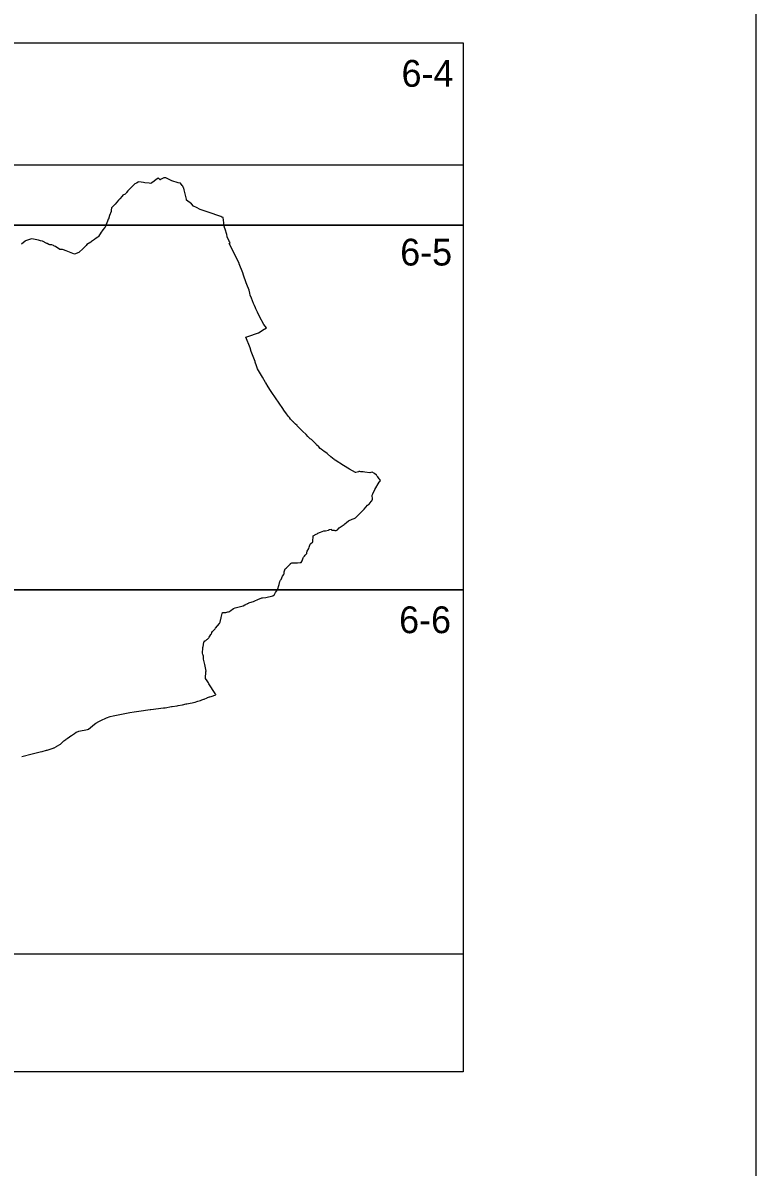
# Model space of a CAD drawing. Extents: x -449577 to -436680, y -1132317 to -1125726.
# Drawn here: x -443806.9 to -443555.6, y -1128354.9 to -1127962.6 of the extents above; entities that cross this region are included whole.
import ezdxf

# ---------------------------------------------------------------- set-up
doc = ezdxf.new("R2010")
doc.units = 0
for name, color, linetype in [('Vrstva 1', 7, 'Continuous'), ('Vrstva 10', 7, 'Continuous'), ('Vrstva 4', 7, 'Continuous')]:
    doc.layers.add(name, color=color, linetype=linetype)

msp = doc.modelspace()

# ---------------------------------------------------------------- linework, layer by layer
at = {"layer": 'Vrstva 1'}
msp.add_lwpolyline([(-445040.56, -1127667.99), (-445040.56, -1128717.99), (-443555.56, -1128717.99), (-443555.56, -1127667.99)], close=True, dxfattribs=at)
msp.add_lwpolyline([(-443807.27, -1128214.11), (-443803.73, -1128213.24), (-443800.96, -1128212.57), (-443800.29, -1128212.36), (-443798.8, -1128212), (-443798.59, -1128211.94), (-443797.16, -1128211.55), (-443796.56, -1128211.29), (-443796.34, -1128211.19), (-443796.18, -1128211.13), (-443795.36, -1128210.68), (-443795.3, -1128210.64), (-443793.99, -1128209.86), (-443792.84, -1128208.81), (-443792.19, -1128208.31), (-443792.06, -1128208.2), (-443792.04, -1128208.19), (-443791.88, -1128208.06), (-443791.73, -1128207.96), (-443790.93, -1128207.4), (-443790.87, -1128207.36), (-443790.8, -1128207.31), (-443790.29, -1128206.96), (-443789.92, -1128206.7), (-443789.26, -1128206.24), (-443788.67, -1128205.83), (-443788.51, -1128205.86), (-443788.5, -1128205.86), (-443788.48, -1128205.84), (-443787.75, -1128205.45), (-443784.79, -1128204.87), (-443784.37, -1128204.72), (-443782.34, -1128203.09), (-443781.87, -1128202.75), (-443781.84, -1128202.73), (-443781.48, -1128202.47), (-443781.3, -1128202.35), (-443779.91, -1128201.65), (-443778.5, -1128201.01), (-443778.2, -1128200.86), (-443776.94, -1128200.4), (-443775.94, -1128200.15), (-443770.23, -1128199.09), (-443768.81, -1128198.83), (-443767.1, -1128198.58), (-443763.23, -1128198.01), (-443762.99, -1128197.98), (-443758.69, -1128197.46), (-443758.16, -1128197.4), (-443756.01, -1128197.04), (-443755.69, -1128196.99), (-443754.03, -1128196.72), (-443753.63, -1128196.65), (-443752.22, -1128196.36), (-443750.93, -1128196.09), (-443750.72, -1128196.05), (-443749.55, -1128195.82), (-443748.88, -1128195.69), (-443748.86, -1128195.69), (-443747.95, -1128195.48), (-443747.88, -1128195.46), (-443747.23, -1128195.3), (-443746.88, -1128195.19), (-443745.99, -1128194.9), (-443745.55, -1128194.75), (-443744.9, -1128194.51), (-443744.78, -1128194.47), (-443743.69, -1128193.98), (-443743.69, -1128193.98), (-443743.57, -1128193.94), (-443742.92, -1128193.71), (-443742.83, -1128193.68), (-443742.4, -1128193.52), (-443740.74, -1128192.94), (-443740.76, -1128192.89), (-443740.87, -1128192.72), (-443741.03, -1128192.49), (-443741.25, -1128192.17), (-443742.95, -1128189.53), (-443743.16, -1128189.18), (-443743.33, -1128188.91), (-443743.77, -1128188.2), (-443744.3, -1128187.35), (-443744.14, -1128184.99), (-443744.13, -1128184.9), (-443744.52, -1128182.6), (-443744.52, -1128182.58), (-443744.53, -1128182.56), (-443744.53, -1128182.56), (-443744.53, -1128182.53), (-443744.94, -1128180.7), (-443744.95, -1128180.51), (-443745.01, -1128179.71), (-443745.11, -1128179.43), (-443745.12, -1128179.41), (-443745.23, -1128179.19), (-443745.27, -1128179.11), (-443745.28, -1128178.73), (-443745.31, -1128178.03), (-443745.26, -1128177.54), (-443745.26, -1128177.52), (-443745.17, -1128176.66), (-443745.15, -1128176.55), (-443744.86, -1128174.91), (-443744.78, -1128174.83), (-443744.48, -1128174.49), (-443744.42, -1128174.42), (-443744.16, -1128174.3), (-443744.1, -1128174.24), (-443743.84, -1128174.04), (-443743.61, -1128173.86), (-443743.4, -1128173.7), (-443743.34, -1128173.66), (-443743.26, -1128173.53), (-443743.18, -1128173.41), (-443743.07, -1128173.24), (-443742.85, -1128172.91), (-443742.43, -1128172.26), (-443742.3, -1128172.01), (-443742.29, -1128172), (-443742.15, -1128171.71), (-443742.1, -1128171.62), (-443741.92, -1128171.29), (-443741.78, -1128171.14), (-443741.48, -1128170.83), (-443741.31, -1128170.65), (-443741.03, -1128170.3), (-443740.9, -1128170.13), (-443740.21, -1128169.28), (-443739.55, -1128168.47), (-443739.26, -1128168.11), (-443739.02, -1128166.94), (-443738.96, -1128166.71), (-443738.89, -1128166.43), (-443738.57, -1128165.12), (-443738.49, -1128164.84), (-443738.49, -1128164.81), (-443738.47, -1128164.76), (-443738.31, -1128164.75), (-443738.29, -1128164.75), (-443738.05, -1128164.75), (-443737.36, -1128164.73), (-443737.35, -1128164.73), (-443737.32, -1128164.73), (-443736.64, -1128164.55), (-443736.44, -1128164.49), (-443736.02, -1128164.38), (-443736, -1128164.37), (-443735.94, -1128164.31), (-443735.64, -1128164.03), (-443735.52, -1128163.95), (-443735.18, -1128163.69), (-443734.76, -1128163.37), (-443734.69, -1128163.35), (-443734.13, -1128163.19), (-443731.43, -1128162.43), (-443730.84, -1128162.16), (-443730.51, -1128162), (-443730.46, -1128161.98), (-443730.36, -1128161.93), (-443730, -1128161.75), (-443729.95, -1128161.73), (-443729.92, -1128161.71), (-443729.91, -1128161.71), (-443729.88, -1128161.69), (-443729.57, -1128161.54), (-443729.51, -1128161.5), (-443729.4, -1128161.45), (-443728.32, -1128161.12), (-443727.89, -1128160.94), (-443727.37, -1128160.72), (-443726.36, -1128160.31), (-443724.94, -1128159.68), (-443724.8, -1128159.67), (-443723.67, -1128159.62), (-443721.27, -1128159.06), (-443720.74, -1128158.66), (-443720.67, -1128158.54), (-443720.58, -1128158.36), (-443720.32, -1128157.85), (-443719.97, -1128157.42), (-443719.95, -1128157.39), (-443719.74, -1128157.1), (-443719.63, -1128156.94), (-443719.62, -1128156.93), (-443719.08, -1128155.15), (-443719.07, -1128155.12), (-443718.87, -1128154.17), (-443718.61, -1128153.71), (-443718.42, -1128153.38), (-443717.87, -1128152.26), (-443717.49, -1128151.75), (-443717.46, -1128151.62), (-443717.39, -1128151.32), (-443717.36, -1128151.18), (-443717.3, -1128150.93), (-443717.28, -1128150.83), (-443716.96, -1128149.82), (-443716.95, -1128149.81), (-443716.66, -1128149.53), (-443716, -1128148.9), (-443715.95, -1128148.85), (-443715.48, -1128148.37), (-443715.22, -1128148.11), (-443715.12, -1128148), (-443714.75, -1128147.68), (-443714.71, -1128147.68), (-443714.7, -1128147.68), (-443714.29, -1128147.67), (-443714.12, -1128147.68), (-443713.49, -1128147.7), (-443712.78, -1128147.7), (-443711.81, -1128147.61), (-443711.78, -1128147.61), (-443711.53, -1128147.58), (-443711.31, -1128147.22), (-443711.26, -1128147.09), (-443711.24, -1128147.04), (-443711.22, -1128146.98), (-443710.86, -1128145.96), (-443710.72, -1128145.79), (-443710.62, -1128145.68), (-443710.58, -1128145.64), (-443710.52, -1128145.56), (-443710.4, -1128145.43), (-443710.13, -1128145.11), (-443710.04, -1128145.01), (-443709.94, -1128144.89), (-443709.6, -1128144.5), (-443709.53, -1128144.11), (-443709.47, -1128143.8), (-443709.4, -1128143.67), (-443708.85, -1128142.75), (-443708.74, -1128142.36), (-443708.55, -1128141.66), (-443708.43, -1128141.37), (-443708.14, -1128141.1), (-443707.59, -1128140.59), (-443707.52, -1128140.53), (-443707.42, -1128138.42), (-443706.4, -1128137.93), (-443706, -1128137.72), (-443705.75, -1128137.59), (-443705.46, -1128137.43), (-443705.24, -1128137.35), (-443704.9, -1128137.22), (-443704.85, -1128137.21), (-443703.76, -1128136.8), (-443703.75, -1128136.8), (-443703.26, -1128136.74), (-443703.18, -1128136.72), (-443702.15, -1128136.46), (-443702, -1128136.42), (-443701.91, -1128136.39), (-443701.74, -1128136.34), (-443701.21, -1128136.17), (-443701.21, -1128136.17), (-443701.2, -1128136.18), (-443701.2, -1128136.18), (-443701.17, -1128136.24), (-443701.04, -1128136.46), (-443700.16, -1128136.56), (-443699.96, -1128136.58), (-443699.6, -1128136.62), (-443699.51, -1128136.58), (-443699.08, -1128136.4), (-443698.43, -1128135.69), (-443696.79, -1128134.53), (-443696.7, -1128134.46), (-443696.53, -1128134.35), (-443696.02, -1128133.93), (-443695.27, -1128133.33), (-443694, -1128132.76), (-443693.38, -1128132.49), (-443692.84, -1128132.25), (-443692.78, -1128132.22), (-443691.13, -1128130.55), (-443690.29, -1128129.66), (-443689.93, -1128129.28), (-443688.74, -1128127.92), (-443688.14, -1128127.46), (-443688.09, -1128127.42), (-443687.25, -1128126.41), (-443687.05, -1128125.84), (-443687.14, -1128124.51), (-443686.92, -1128124.02), (-443686.28, -1128122.57), (-443684.82, -1128120.09), (-443684.79, -1128120.04), (-443684.79, -1128120.04), (-443684.77, -1128120.01), (-443684.74, -1128119.97), (-443684.59, -1128119.78), (-443684.33, -1128119.44), (-443684.59, -1128119.14), (-443684.73, -1128118.92), (-443685.2, -1128118.18), (-443685.4, -1128117.99), (-443685.55, -1128117.83), (-443685.74, -1128117.63), (-443686.32, -1128117.06), (-443687.17, -1128116.59), (-443687.62, -1128116.77), (-443687.95, -1128116.89), (-443689.7, -1128116.62), (-443690.31, -1128116.53), (-443690.45, -1128116.52), (-443691.04, -1128116.5), (-443691.42, -1128116.45), (-443691.58, -1128116.42), (-443691.62, -1128116.42), (-443691.65, -1128116.41), (-443691.65, -1128116.41), (-443691.68, -1128116.42), (-443691.78, -1128116.45), (-443691.91, -1128116.48), (-443692.81, -1128116.72), (-443692.88, -1128116.69), (-443694.95, -1128115.65), (-443696.97, -1128114.37), (-443699.88, -1128112.55), (-443700.04, -1128112.41), (-443700.08, -1128112.38), (-443700.17, -1128112.3), (-443701.31, -1128111.37), (-443702.46, -1128110.32), (-443702.57, -1128110.22), (-443703.78, -1128109.46), (-443704.06, -1128109.23), (-443704.69, -1128108.73), (-443705, -1128108.49), (-443705.5, -1128107.96), (-443706.22, -1128107.2), (-443706.37, -1128107.04), (-443706.83, -1128106.55), (-443707.8, -1128105.52), (-443708, -1128105.41), (-443708, -1128105.41), (-443708.18, -1128105.32), (-443708.38, -1128105.22), (-443709.21, -1128104.39), (-443709.84, -1128103.76), (-443711.02, -1128102.59), (-443711.95, -1128101.65), (-443712.11, -1128101.5), (-443712.55, -1128101.05), (-443712.79, -1128100.81), (-443712.88, -1128100.72), (-443712.92, -1128100.68), (-443713.44, -1128100.16), (-443714.08, -1128099.51), (-443714.16, -1128099.43), (-443714.18, -1128099.41), (-443714.33, -1128099.26), (-443715.16, -1128098.42), (-443715.54, -1128097.92), (-443715.82, -1128097.55), (-443716.14, -1128097.12), (-443716.5, -1128096.64), (-443717.45, -1128095.38), (-443717.82, -1128094.84), (-443720.36, -1128091.1), (-443720.53, -1128090.84), (-443721.3, -1128089.65), (-443721.97, -1128088.64), (-443722.81, -1128087.31), (-443723.61, -1128086.04), (-443723.69, -1128085.91), (-443724.78, -1128084.06), (-443726.46, -1128081.21), (-443726.46, -1128081.2), (-443726.46, -1128081.2), (-443726.47, -1128081.2), (-443726.8, -1128080.22), (-443727.25, -1128078.92), (-443727.31, -1128078.72), (-443728.69, -1128075.21), (-443728.98, -1128073.96), (-443730.46, -1128070.28), (-443729.83, -1128070.08), (-443726.11, -1128068.84), (-443724.14, -1128067.62), (-443723.96, -1128067.51), (-443723.9, -1128067.47), (-443723.7, -1128067.35), (-443723.43, -1128067.18), (-443724.35, -1128065.99), (-443725.76, -1128063.21), (-443726.51, -1128061.74), (-443727.04, -1128060.58), (-443727.06, -1128060.54), (-443727.12, -1128060.41), (-443727.13, -1128060.38), (-443727.15, -1128060.35), (-443727.19, -1128060.26), (-443727.52, -1128059.53), (-443727.84, -1128058.74), (-443728.55, -1128056.97), (-443728.96, -1128055.93), (-443729.11, -1128055.3), (-443729.37, -1128054.17), (-443730.11, -1128052.28), (-443730.31, -1128051.68), (-443731.25, -1128049.05), (-443731.52, -1128048.33), (-443732.71, -1128045.24), (-443732.78, -1128045.06), (-443732.81, -1128044.98), (-443736.16, -1128038.17), (-443735.85, -1128038.03), (-443735.83, -1128038.02), (-443735.93, -1128037.85), (-443736.01, -1128037.75), (-443736.18, -1128037.52), (-443736.24, -1128037.44), (-443736.85, -1128035.96), (-443736.9, -1128035.67), (-443737, -1128035.21), (-443737.01, -1128035.15), (-443737.52, -1128033.31), (-443737.82, -1128032.68), (-443737.83, -1128032.6), (-443737.87, -1128032.24), (-443738.01, -1128031.15), (-443738.29, -1128029.31), (-443738.35, -1128029.29), (-443738.65, -1128029.19), (-443739.03, -1128028.93), (-443739.04, -1128028.93), (-443743.34, -1128027.52), (-443746.13, -1128026.54), (-443747.44, -1128025.92), (-443748.41, -1128025.36), (-443749.13, -1128024.58), (-443750.81, -1128023.31), (-443750.87, -1128023.01), (-443751.45, -1128020.31), (-443751.6, -1128019.77), (-443751.78, -1128019.26), (-443751.83, -1128019.1), (-443752.08, -1128018.58), (-443752.33, -1128018.27), (-443752.91, -1128017.58), (-443753.66, -1128017.37), (-443755.84, -1128016.71), (-443757.93, -1128015.75), (-443758.55, -1128015.75), (-443759.5, -1128016.12), (-443759.63, -1128016.21), (-443759.7, -1128016.26), (-443759.84, -1128016.36), (-443759.88, -1128016.39), (-443759.9, -1128016.37), (-443760.11, -1128016.12), (-443760.36, -1128015.84), (-443760.44, -1128015.74), (-443760.53, -1128015.78), (-443761.04, -1128016.17), (-443761.23, -1128016.32), (-443761.9, -1128016.84), (-443762.65, -1128017.4), (-443762.99, -1128017.62), (-443763.58, -1128017.58), (-443765.06, -1128017.43), (-443765.52, -1128017.34), (-443767.11, -1128017.02), (-443767.41, -1128017.13), (-443767.97, -1128017.48), (-443768.52, -1128017.8), (-443769.01, -1128018.26), (-443769.54, -1128018.75), (-443769.94, -1128019.14), (-443769.95, -1128019.15), (-443770.28, -1128019.49), (-443770.41, -1128019.63), (-443770.92, -1128020.18), (-443771.37, -1128020.73), (-443771.53, -1128020.92), (-443771.89, -1128021.35), (-443772.63, -1128021.68), (-443772.65, -1128021.68), (-443772.85, -1128021.93), (-443773.71, -1128022.95), (-443774.09, -1128023.4), (-443775.22, -1128024.76), (-443775.23, -1128024.77), (-443776.47, -1128025.94), (-443776.59, -1128026.78), (-443776.64, -1128027.15), (-443776.68, -1128027.25), (-443777.16, -1128028.6), (-443777.6, -1128029.84), (-443777.63, -1128029.92), (-443777.93, -1128030.61), (-443778.86, -1128032.79), (-443778.88, -1128032.8), (-443779.45, -1128033.48), (-443779.75, -1128033.83), (-443779.75, -1128033.84), (-443780.09, -1128034.38), (-443780.96, -1128035.77), (-443781.05, -1128035.91), (-443781.22, -1128036.04), (-443781.75, -1128036.43), (-443782.36, -1128036.88), (-443782.36, -1128036.88), (-443783.33, -1128037.51), (-443783.46, -1128037.6), (-443783.64, -1128037.72), (-443784.94, -1128038.58), (-443784.95, -1128038.59), (-443785.21, -1128038.85), (-443785.33, -1128038.97), (-443785.55, -1128039.2), (-443785.83, -1128039.48), (-443786.4, -1128040.05), (-443787.56, -1128041.21), (-443787.76, -1128041.29), (-443789.26, -1128041.86), (-443792.07, -1128040.74), (-443792.07, -1128040.75), (-443792.08, -1128040.77), (-443792.99, -1128040.39), (-443793.3, -1128040.26), (-443793.32, -1128040.26), (-443793.71, -1128040.26), (-443794.19, -1128040.26), (-443795.75, -1128039.27), (-443796.01, -1128039.14), (-443796.3, -1128038.98), (-443796.36, -1128038.95), (-443796.4, -1128038.93), (-443796.94, -1128038.7), (-443796.99, -1128038.7), (-443797, -1128038.7), (-443797.15, -1128038.69), (-443797.27, -1128038.68), (-443797.58, -1128038.66), (-443797.6, -1128038.66), (-443797.6, -1128038.66), (-443797.71, -1128038.62), (-443797.95, -1128038.52), (-443798.55, -1128038.27), (-443798.71, -1128038.2), (-443800.23, -1128037.47), (-443800.85, -1128037.29), (-443801.52, -1128037.09), (-443803.84, -1128036.66), (-443803.85, -1128036.66), (-443804.25, -1128036.77), (-443805.99, -1128037.35), (-443806.12, -1128037.46), (-443807.33, -1128038.42)], dxfattribs=at)
at = {"layer": 'Vrstva 10'}
msp.add_lwpolyline([(-443655.97, -1128011.25), (-443655.97, -1128322.23), (-443988.84, -1128322.23), (-443988.84, -1128156.93), (-443968.47, -1128156.93), (-443968.47, -1128031.93), (-443968.47, -1128011.25), (-443655.97, -1128011.25)], dxfattribs=at)
at = {"layer": 'Vrstva 4'}
msp.add_line((-443968.47, -1127969.43), (-443655.97, -1127969.43), dxfattribs=at)
msp.add_lwpolyline([(-443655.97, -1127969.43), (-443655.97, -1128031.93), (-443812.22, -1128031.93), (-443812.22, -1127969.43)], dxfattribs=at)
for points in [[(-443655.97, -1128031.93), (-443655.97, -1128156.93), (-443812.22, -1128156.93), (-443812.22, -1128031.93)], [(-443655.97, -1128156.93), (-443655.97, -1128281.93), (-443812.22, -1128281.93), (-443812.22, -1128156.93)]]:
    msp.add_lwpolyline(points, close=True, dxfattribs=at)

# ---------------------------------------------------------------- texts
at = {"layer": 'Vrstva 1'}
for s, p in [('6-4', (-443677.1, -1127984.48)), ('6-5', (-443677.55, -1128045.77)), ('6-6', (-443677.92, -1128171.84))]:
    msp.add_text(s, height=9.2, dxfattribs=at).set_placement(p)

doc.saveas('drawing.dxf')
